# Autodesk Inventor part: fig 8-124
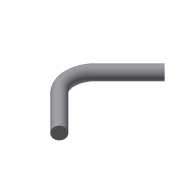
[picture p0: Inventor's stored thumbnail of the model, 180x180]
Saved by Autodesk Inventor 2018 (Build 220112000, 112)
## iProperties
Created: 2007-02
Part Number: fig 8-124
Document SubType Name: Modeling
Designer: Administrator
Density: 1 g/cm^3
Material: Generic
Appearance: Default
Author: Administrator
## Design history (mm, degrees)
node "Sketch1"
sketch "Sketch2"
  geometry: C1 r 5 at (0, 0); 1 further point
  constraints: 1 centre point, 1 coincident, 1 other
  dimensions: "d0" = 10 diameter of C1
extrude "Extrusion1" new body sketch "Sketch2" stored distance "d1" = 100; taper "d2" = 0 deg
workplane "Work Plane1"
sketch "Sketch3"
  geometry: L1 (0, 11)-(0, -8)
  constraints: 2 end point, 1 vertical
feature "Bend Part2" sketch "Sketch3" dims "d5" = 15, "d6" = 90 deg
body "Solid1"
